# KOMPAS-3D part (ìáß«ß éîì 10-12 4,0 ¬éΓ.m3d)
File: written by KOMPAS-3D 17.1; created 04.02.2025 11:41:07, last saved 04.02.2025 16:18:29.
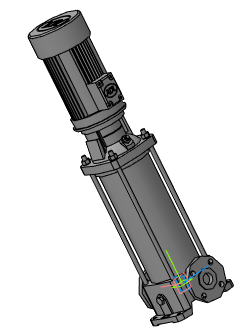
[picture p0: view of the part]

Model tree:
1. Операция без истории:2  (labels: Насос ВМН 10-12 4,0 кВт)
